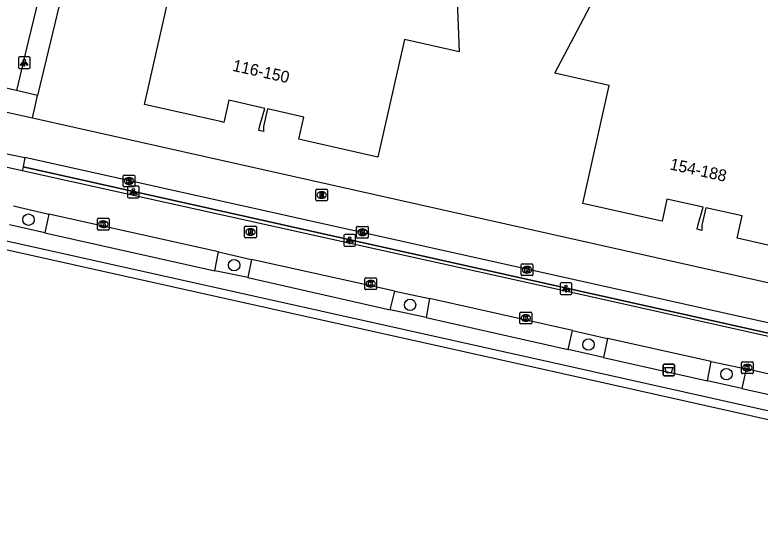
# Model space of a CAD drawing. Extents: x 162172 to 163187, y 382874 to 383684.
# Drawn here: x 162266.4 to 162330.1, y 383053.2 to 383097.4 of the extents above; entities that cross this region are included whole.
import ezdxf

# ---------------------------------------------------------------- set-up
doc = ezdxf.new("R2010")
doc.units = 0
for name, color, linetype in [('IMGEO_Afvalbak', 7, 'Continuous'), ('IMGEO_Boom', 7, 'Continuous'), ('IMGEO_Fietspad_open', 7, 'Continuous'), ('IMGEO_Kademuur', 7, 'Continuous'), ('IMGEO_Kolk', 7, 'Continuous'), ('IMGEO_Lichtpunt', 7, 'Continuous'), ('IMGEO_Muur', 7, 'Continuous'), ('IMGEO_Pand', 7, 'Continuous'), ('IMGEO_Pand_nummerreeks', 7, 'Continuous'), ('IMGEO_Rijbaan_lokaal_open', 7, 'Continuous'), ('IMGEO_Rioolput', 7, 'Continuous'), ('IMGEO_Verkeerseiland_open', 7, 'Continuous'), ('IMGEO_Voetpad_open', 7, 'Continuous')]:
    doc.layers.add(name, color=color, linetype=linetype)

msp = doc.modelspace()

# ---------------------------------------------------------------- linework, layer by layer
at = {"layer": 'IMGEO_Afvalbak'}
for p, q in [((162321.804, 383066.7), (162321.804, 383067.5)), ((162321.804, 383067.5), (162321.804, 383066.7)), ((162321.904, 383067.6), (162322.694, 383067.6)), ((162322.694, 383067.6), (162321.904, 383067.6)), ((162322.794, 383067.5), (162322.794, 383066.7)), ((162322.794, 383066.7), (162322.794, 383067.5)), ((162322.694, 383066.6), (162321.904, 383066.6)), ((162321.904, 383066.6), (162322.694, 383066.6))]:
    msp.add_line(p, q, dxfattribs=at)
msp.add_lwpolyline([(162321.947, 383067.314), (162322.651, 383067.314), (162322.502, 383066.844), (162322.096, 383066.844), (162321.947, 383067.314)], dxfattribs=at)
for centre, start, end in [((162321.904, 383067.5), 90, 180), ((162321.904, 383067.5), 90, 180), ((162322.694, 383067.5), 0, 90), ((162322.694, 383067.5), 360, 90), ((162321.904, 383066.7), 180, 270), ((162321.904, 383066.7), 180, 270), ((162322.694, 383066.7), 270, 0), ((162322.694, 383066.7), 270, 0)]:
    msp.add_arc(centre, 0.1, start, end, dxfattribs=at)
at = {"layer": 'IMGEO_Boom'}
for centre in [(162267.581, 383079.948), (162285.155, 383076.059), (162300.19, 383072.66), (162315.434, 383069.272), (162327.222, 383066.74)]:
    msp.add_circle(centre, 0.489, dxfattribs=at)
at = {"layer": 'IMGEO_Fietspad_open'}
for points in [[(162267.056, 383084.129), (162265.12, 383084.559)], [(162266.293, 383081.12), (162269.32, 383080.413)], [(162283.824, 383077.204), (162269.32, 383080.413)], [(162283.824, 383077.204), (162286.631, 383076.546)], [(162298.895, 383073.827), (162286.631, 383076.546)], [(162298.895, 383073.827), (162301.862, 383073.209)], [(162314.064, 383070.471), (162301.862, 383073.209)], [(162314.064, 383070.471), (162317.059, 383069.805)], [(162325.931, 383067.815), (162317.059, 383069.805)], [(162325.931, 383067.815), (162328.897, 383067.213)], [(162337.993, 383065.091), (162328.897, 383067.213)]]:
    msp.add_lwpolyline(points, dxfattribs=at)
at = {"layer": 'IMGEO_Kademuur'}
for points in [[(162182.996, 383097.146), (162183.031, 383097.321), (162187.251, 383096.286), (162188.296, 383095.38), (162313.416, 383067.527), (162541.309, 383016.586)], [(162569.19, 383010.669), (162568.136, 383009.792), (162380.82, 383051.66), (162313.239, 383066.765), (162187.94, 383094.645), (162186.014, 383096.385), (162186.034, 383096.464), (162182.996, 383097.146)]]:
    msp.add_lwpolyline(points, dxfattribs=at)
at = {"layer": 'IMGEO_Kolk'}
for p, q in [((162275.75, 383083.756), (162276.602, 383083.756)), ((162275.675, 383082.83), (162275.675, 383083.682)), ((162276.163, 383083.536), (162276.188, 383083.536)), ((162276.676, 383083.682), (162276.676, 383082.83)), ((162276.602, 383082.756), (162275.75, 383082.756)), ((162276.186, 383082.976), (162276.161, 383082.976)), ((162273.482, 383079.135), (162273.482, 383079.987)), ((162273.557, 383080.061), (162274.409, 383080.061)), ((162274.483, 383079.987), (162274.483, 383079.135)), ((162273.993, 383079.281), (162273.968, 383079.281)), ((162273.97, 383079.841), (162273.995, 383079.841)), ((162295.622, 383078.445), (162295.622, 383079.297)), ((162295.697, 383079.371), (162296.549, 383079.371)), ((162296.623, 383079.297), (162296.623, 383078.445)), ((162274.409, 383079.061), (162273.557, 383079.061)), ((162296.11, 383079.151), (162296.135, 383079.151)), ((162296.549, 383078.371), (162295.697, 383078.371)), ((162296.133, 383078.591), (162296.108, 383078.591)), ((162309.684, 383075.236), (162309.684, 383076.088)), ((162309.759, 383076.162), (162310.611, 383076.162)), ((162310.685, 383076.088), (162310.685, 383075.236)), ((162310.172, 383075.942), (162310.197, 383075.942)), ((162296.328, 383074.044), (162296.328, 383074.896)), ((162296.403, 383074.97), (162297.255, 383074.97)), ((162297.329, 383074.896), (162297.329, 383074.044)), ((162310.611, 383075.162), (162309.759, 383075.162)), ((162310.195, 383075.382), (162310.17, 383075.382)), ((162296.839, 383074.19), (162296.814, 383074.19)), ((162296.816, 383074.75), (162296.841, 383074.75)), ((162297.255, 383073.97), (162296.403, 383073.97)), ((162309.582, 383071.114), (162309.582, 383071.966)), ((162309.657, 383072.04), (162310.509, 383072.04)), ((162310.07, 383071.82), (162310.095, 383071.82)), ((162310.583, 383071.966), (162310.583, 383071.114)), ((162310.509, 383071.04), (162309.657, 383071.04)), ((162310.093, 383071.26), (162310.068, 383071.26)), ((162328.509, 383066.862), (162328.509, 383067.714)), ((162328.584, 383067.788), (162329.436, 383067.788)), ((162328.997, 383067.568), (162329.022, 383067.568)), ((162329.51, 383067.714), (162329.51, 383066.862)), ((162329.436, 383066.788), (162328.584, 383066.788)), ((162329.02, 383067.008), (162328.995, 383067.008))]:
    msp.add_line(p, q, dxfattribs=at)
for points in [[(162275.75, 383083.756), (162276.602, 383083.756)], [(162275.675, 383082.83), (162275.675, 383083.682)], [(162275.996, 383083.456), (162276.119, 383083.456), (162276.119, 383083.305), (162276.249, 383083.456), (162276.413, 383083.456), (162276.267, 383083.305), (162276.42, 383083.056), (162276.268, 383083.056), (162276.183, 383083.22), (162276.119, 383083.153), (162276.119, 383083.056), (162275.996, 383083.056), (162275.996, 383083.456)], [(162276.676, 383083.682), (162276.676, 383082.83)], [(162276.602, 383082.756), (162275.75, 383082.756)], [(162273.482, 383079.135), (162273.482, 383079.987)], [(162273.557, 383080.061), (162274.409, 383080.061)], [(162274.483, 383079.987), (162274.483, 383079.135)], [(162273.803, 383079.761), (162273.926, 383079.761), (162273.926, 383079.61), (162274.056, 383079.761), (162274.22, 383079.761), (162274.074, 383079.61), (162274.227, 383079.361), (162274.075, 383079.361), (162273.99, 383079.525), (162273.926, 383079.458), (162273.926, 383079.361), (162273.803, 383079.361), (162273.803, 383079.761)], [(162295.622, 383078.445), (162295.622, 383079.297)], [(162295.697, 383079.371), (162296.549, 383079.371)], [(162296.623, 383079.297), (162296.623, 383078.445)], [(162274.409, 383079.061), (162273.557, 383079.061)], [(162295.943, 383079.071), (162296.066, 383079.071), (162296.066, 383078.92), (162296.196, 383079.071), (162296.36, 383079.071), (162296.214, 383078.92), (162296.367, 383078.671), (162296.215, 383078.671), (162296.13, 383078.835), (162296.066, 383078.768), (162296.066, 383078.671), (162295.943, 383078.671), (162295.943, 383079.071)], [(162296.549, 383078.371), (162295.697, 383078.371)], [(162309.684, 383075.236), (162309.684, 383076.088)], [(162309.759, 383076.162), (162310.611, 383076.162)], [(162310.685, 383076.088), (162310.685, 383075.236)], [(162310.005, 383075.862), (162310.128, 383075.862), (162310.128, 383075.711), (162310.258, 383075.862), (162310.422, 383075.862), (162310.276, 383075.711), (162310.429, 383075.462), (162310.277, 383075.462), (162310.192, 383075.626), (162310.128, 383075.559), (162310.128, 383075.462), (162310.005, 383075.462), (162310.005, 383075.862)], [(162296.328, 383074.044), (162296.328, 383074.896)], [(162296.403, 383074.97), (162297.255, 383074.97)], [(162297.329, 383074.896), (162297.329, 383074.044)], [(162310.611, 383075.162), (162309.759, 383075.162)], [(162296.649, 383074.67), (162296.772, 383074.67), (162296.772, 383074.519), (162296.902, 383074.67), (162297.066, 383074.67), (162296.92, 383074.519), (162297.073, 383074.27), (162296.921, 383074.27), (162296.836, 383074.434), (162296.772, 383074.367), (162296.772, 383074.27), (162296.649, 383074.27), (162296.649, 383074.67)], [(162297.255, 383073.97), (162296.403, 383073.97)], [(162309.582, 383071.114), (162309.582, 383071.966)], [(162309.657, 383072.04), (162310.509, 383072.04)], [(162309.903, 383071.74), (162310.026, 383071.74), (162310.026, 383071.589), (162310.156, 383071.74), (162310.32, 383071.74), (162310.174, 383071.589), (162310.327, 383071.34), (162310.175, 383071.34), (162310.09, 383071.504), (162310.026, 383071.437), (162310.026, 383071.34), (162309.903, 383071.34), (162309.903, 383071.74)], [(162310.583, 383071.966), (162310.583, 383071.114)], [(162310.509, 383071.04), (162309.657, 383071.04)], [(162328.509, 383066.862), (162328.509, 383067.714)], [(162328.584, 383067.788), (162329.436, 383067.788)], [(162328.83, 383067.488), (162328.953, 383067.488), (162328.953, 383067.337), (162329.083, 383067.488), (162329.247, 383067.488), (162329.101, 383067.337), (162329.254, 383067.088), (162329.102, 383067.088), (162329.017, 383067.252), (162328.953, 383067.185), (162328.953, 383067.088), (162328.83, 383067.088), (162328.83, 383067.488)], [(162329.51, 383067.714), (162329.51, 383066.862)], [(162329.436, 383066.788), (162328.584, 383066.788)]]:
    msp.add_lwpolyline(points, dxfattribs=at)
for centre, start, end in [((162275.752, 383083.68), 91.55205, 178.44795), ((162275.752, 383083.68), 91.55205, 178.44795), ((162276.6, 383083.68), 1.55205, 88.44795), ((162276.6, 383083.68), 1.55205, 88.44795), ((162275.752, 383082.832), 181.55205, 268.44795), ((162275.752, 383082.832), 181.55205, 268.44795), ((162276.6, 383082.832), 271.55205, 358.44795), ((162276.6, 383082.832), 271.55205, 358.44795), ((162273.559, 383079.985), 91.55205, 178.44795), ((162273.559, 383079.985), 91.55205, 178.44795), ((162274.407, 383079.985), 1.55205, 88.44795), ((162274.407, 383079.985), 1.55205, 88.44795), ((162295.699, 383079.295), 91.55205, 178.44795), ((162295.699, 383079.295), 91.55205, 178.44795), ((162296.547, 383079.295), 1.55205, 88.44795), ((162296.547, 383079.295), 1.55205, 88.44795), ((162273.559, 383079.137), 181.55205, 268.44795), ((162273.559, 383079.137), 181.55205, 268.44795), ((162274.407, 383079.137), 271.55205, 358.44795), ((162274.407, 383079.137), 271.55205, 358.44795), ((162295.699, 383078.447), 181.55205, 268.44795), ((162295.699, 383078.447), 181.55205, 268.44795), ((162296.547, 383078.447), 271.55205, 358.44795), ((162296.547, 383078.447), 271.55205, 358.44795), ((162309.761, 383076.086), 91.55205, 178.44795), ((162309.761, 383076.086), 91.55205, 178.44795), ((162310.609, 383076.086), 1.55205, 88.44795), ((162310.609, 383076.086), 1.55205, 88.44795), ((162296.405, 383074.894), 91.55205, 178.44795), ((162296.405, 383074.894), 91.55205, 178.44795), ((162297.253, 383074.894), 1.55205, 88.44795), ((162297.253, 383074.894), 1.55205, 88.44795), ((162309.761, 383075.238), 181.55205, 268.44795), ((162309.761, 383075.238), 181.55205, 268.44795), ((162310.609, 383075.238), 271.55205, 358.44795), ((162310.609, 383075.238), 271.55205, 358.44795), ((162296.405, 383074.046), 181.55205, 268.44795), ((162296.405, 383074.046), 181.55205, 268.44795), ((162297.253, 383074.046), 271.55205, 358.44795), ((162297.253, 383074.046), 271.55205, 358.44795), ((162309.659, 383071.964), 91.55205, 178.44795), ((162309.659, 383071.964), 91.55205, 178.44795), ((162310.507, 383071.964), 1.55205, 88.44795), ((162310.507, 383071.964), 1.55205, 88.44795), ((162309.659, 383071.116), 181.55205, 268.44795), ((162309.659, 383071.116), 181.55205, 268.44795), ((162310.507, 383071.116), 271.55205, 358.44795), ((162310.507, 383071.116), 271.55205, 358.44795), ((162328.586, 383067.712), 91.55205, 178.44795), ((162328.586, 383067.712), 91.55205, 178.44795), ((162329.434, 383067.712), 1.55205, 88.44795), ((162329.434, 383067.712), 1.55205, 88.44795), ((162328.586, 383066.864), 181.55205, 268.44795), ((162328.586, 383066.864), 181.55205, 268.44795), ((162329.434, 383066.864), 271.55205, 358.44795), ((162329.434, 383066.864), 271.55205, 358.44795)]:
    msp.add_arc(centre, 0.0765, start, end, dxfattribs=at)
for centre, major_axis, ratio, start_param, end_param in [((162276.162, 383083.256), (-0.387, 0.002), 0.722429, 4.712389, 7.853982), ((162276.187, 383083.256), (-0.39, 0.002), 0.717154, 1.570796, 4.712389), ((162273.969, 383079.561), (-0.387, 0.002), 0.722429, 4.712389, 7.853982), ((162273.994, 383079.561), (-0.39, 0.002), 0.717154, 1.570796, 4.712389), ((162296.109, 383078.871), (-0.387, 0.002), 0.722429, 4.712389, 7.853982), ((162296.134, 383078.871), (-0.39, 0.002), 0.717154, 1.570796, 4.712389), ((162310.171, 383075.662), (-0.387, 0.002), 0.722429, 4.712389, 7.853982), ((162310.196, 383075.662), (-0.39, 0.002), 0.717154, 1.570796, 4.712389), ((162296.815, 383074.47), (-0.387, 0.002), 0.722429, 4.712389, 7.853982), ((162296.84, 383074.47), (-0.39, 0.002), 0.717154, 1.570796, 4.712389), ((162310.069, 383071.54), (-0.387, 0.002), 0.722429, 4.712389, 7.853982), ((162310.094, 383071.54), (-0.39, 0.002), 0.717154, 1.570796, 4.712389), ((162328.996, 383067.288), (-0.387, 0.002), 0.722429, 4.712389, 7.853982), ((162329.021, 383067.288), (-0.39, 0.002), 0.717154, 1.570796, 4.712389)]:
    msp.add_ellipse(centre, major_axis=major_axis, ratio=ratio, start_param=start_param, end_param=end_param, dxfattribs=at)
at = {"layer": 'IMGEO_Lichtpunt'}
for p, q in [((162266.723, 383093.756), (162266.723, 383092.949)), ((162266.723, 383093.756), (162266.723, 383092.949)), ((162267.625, 383093.851), (162266.817, 383093.851)), ((162267.625, 383093.851), (162266.817, 383093.851)), ((162267.719, 383092.949), (162267.719, 383093.756)), ((162267.719, 383092.949), (162267.719, 383093.756)), ((162266.817, 383092.855), (162267.625, 383092.855)), ((162266.817, 383092.855), (162267.625, 383092.855)), ((162276.054, 383082.707), (162276.054, 383081.9)), ((162276.054, 383082.707), (162276.054, 383081.9)), ((162276.956, 383082.802), (162276.148, 383082.802)), ((162276.956, 383082.802), (162276.148, 383082.802)), ((162277.05, 383081.9), (162277.05, 383082.707)), ((162277.05, 383081.9), (162277.05, 383082.707)), ((162276.148, 383081.806), (162276.956, 383081.806)), ((162276.148, 383081.806), (162276.956, 383081.806)), ((162295.425, 383078.683), (162294.617, 383078.683)), ((162295.425, 383078.683), (162294.617, 383078.683)), ((162294.523, 383078.588), (162294.523, 383077.781)), ((162294.523, 383078.588), (162294.523, 383077.781)), ((162295.519, 383077.781), (162295.519, 383078.588)), ((162295.519, 383077.781), (162295.519, 383078.588)), ((162294.617, 383077.687), (162295.425, 383077.687)), ((162294.617, 383077.687), (162295.425, 383077.687)), ((162313.02, 383074.466), (162313.02, 383073.659)), ((162313.02, 383074.466), (162313.02, 383073.659)), ((162313.922, 383074.561), (162313.114, 383074.561)), ((162313.922, 383074.561), (162313.114, 383074.561)), ((162314.016, 383073.659), (162314.016, 383074.466)), ((162314.016, 383073.659), (162314.016, 383074.466)), ((162313.114, 383073.565), (162313.922, 383073.565)), ((162313.114, 383073.565), (162313.922, 383073.565))]:
    msp.add_line(p, q, dxfattribs=at)
for points in [[(162267.097, 383093.42), (162267.136, 383093.392), (162266.948, 383093.13), (162266.91, 383093.157), (162267.097, 383093.42)], [(162267.199, 383093.372), (162267.246, 383093.372), (162267.246, 383093.05), (162267.199, 383093.05), (162267.199, 383093.372)], [(162267.309, 383093.392), (162267.347, 383093.419), (162267.534, 383093.157), (162267.495, 383093.129), (162267.309, 383093.392)], [(162276.428, 383082.371), (162276.467, 383082.343), (162276.279, 383082.081), (162276.241, 383082.108), (162276.428, 383082.371)], [(162276.53, 383082.323), (162276.577, 383082.323), (162276.577, 383082.001), (162276.53, 383082.001), (162276.53, 383082.323)], [(162276.64, 383082.343), (162276.678, 383082.37), (162276.865, 383082.108), (162276.826, 383082.08), (162276.64, 383082.343)], [(162294.897, 383078.252), (162294.936, 383078.224), (162294.748, 383077.962), (162294.71, 383077.989), (162294.897, 383078.252)], [(162294.999, 383078.204), (162295.046, 383078.204), (162295.046, 383077.882), (162294.999, 383077.882), (162294.999, 383078.204)], [(162295.109, 383078.224), (162295.147, 383078.251), (162295.334, 383077.989), (162295.295, 383077.961), (162295.109, 383078.224)], [(162313.394, 383074.13), (162313.433, 383074.102), (162313.245, 383073.84), (162313.207, 383073.867), (162313.394, 383074.13)], [(162313.496, 383074.082), (162313.543, 383074.082), (162313.543, 383073.76), (162313.496, 383073.76), (162313.496, 383074.082)], [(162313.606, 383074.102), (162313.644, 383074.129), (162313.831, 383073.867), (162313.792, 383073.839), (162313.606, 383074.102)]]:
    msp.add_lwpolyline(points, dxfattribs=at)
for centre in [(162267.222, 383093.554), (162276.553, 383082.505), (162295.022, 383078.386), (162313.519, 383074.264)]:
    msp.add_circle(centre, 0.0994, dxfattribs=at)
for centre, start, end in [((162266.817, 383093.756), 90, 180), ((162266.817, 383093.756), 90, 180), ((162267.625, 383093.756), 0, 90), ((162267.625, 383093.756), 0, 90), ((162266.817, 383092.949), 180, 270), ((162266.817, 383092.949), 180, 270), ((162267.625, 383092.949), 270, 0), ((162267.625, 383092.949), 270, 360), ((162276.148, 383082.707), 90, 180), ((162276.148, 383082.707), 90, 180), ((162276.956, 383082.707), 0, 90), ((162276.956, 383082.707), 0, 90), ((162276.148, 383081.9), 180, 270), ((162276.148, 383081.9), 180, 270), ((162276.956, 383081.9), 270, 0), ((162276.956, 383081.9), 270, 360), ((162294.617, 383078.588), 90, 180), ((162294.617, 383078.588), 90, 180), ((162295.425, 383078.588), 0, 90), ((162295.425, 383078.588), 0, 90), ((162294.617, 383077.781), 180, 270), ((162294.617, 383077.781), 180, 270), ((162295.425, 383077.781), 270, 0), ((162295.425, 383077.781), 270, 360), ((162313.114, 383074.466), 90, 180), ((162313.114, 383074.466), 90, 180), ((162313.922, 383074.466), 0, 90), ((162313.922, 383074.466), 0, 90), ((162313.114, 383073.659), 180, 270), ((162313.114, 383073.659), 180, 270), ((162313.922, 383073.659), 270, 0), ((162313.922, 383073.659), 270, 360)]:
    msp.add_arc(centre, 0.0946, start, end, dxfattribs=at)
at = {"layer": 'IMGEO_Muur'}
msp.add_lwpolyline([(162387.584, 383057.578), (162267.118, 383084.469)], dxfattribs=at)
at = {"layer": 'IMGEO_Pand'}
for points in [[(162303.917, 383106.01), (162304.381, 383094.3), (162299.71, 383095.354), (162297.444, 383085.285), (162290.928, 383086.759), (162290.681, 383086.815), (162291.107, 383088.717), (162288.013, 383089.41), (162287.678, 383087.917), (162287.68, 383087.475), (162287.26, 383087.569), (162287.354, 383087.988), (162287.785, 383089.458), (162284.691, 383090.151), (162284.266, 383088.259), (162283.986, 383088.323), (162277.508, 383089.793), (162279.771, 383099.862), (162275.11, 383100.906), (162280.553, 383111.29)], [(162341.366, 383097.566), (162341.833, 383085.858), (162337.163, 383086.917), (162334.903, 383076.836), (162328.404, 383078.31), (162328.134, 383078.371), (162328.56, 383080.273), (162325.466, 383080.966), (162325.131, 383079.473), (162325.133, 383079.031), (162324.713, 383079.125), (162324.807, 383079.544), (162325.238, 383081.014), (162322.144, 383081.707), (162321.72, 383079.816), (162321.455, 383079.876), (162314.948, 383081.342), (162317.212, 383091.411), (162312.553, 383092.454), (162318.021, 383102.852)]]:
    msp.add_lwpolyline(points, dxfattribs=at)
at = {"layer": 'IMGEO_Rijbaan_lokaal_open'}
for points in [[(162234.912, 383095.955), (162267.92, 383088.659)], [(162267.92, 383088.659), (162389.018, 383061.534)], [(162265.344, 383085.659), (162267.262, 383085.257)], [(162387.584, 383057.578), (162387.741, 383058.335), (162385.606, 383058.831), (162369.028, 383062.601), (162267.262, 383085.257)], [(162267.118, 383084.469), (162267.056, 383084.129)], [(162267.118, 383084.469), (162387.584, 383057.578)], [(162543.781, 383022.666), (162543.703, 383022.357), (162314.763, 383073.543), (162267.056, 383084.129)]]:
    msp.add_lwpolyline(points, dxfattribs=at)
at = {"layer": 'IMGEO_Rioolput'}
for p, q in [((162292.138, 383081.629), (162292.138, 383082.481)), ((162292.213, 383082.555), (162293.065, 383082.555)), ((162293.139, 383082.481), (162293.139, 383081.629)), ((162292.626, 383082.335), (162292.651, 383082.335)), ((162293.065, 383081.555), (162292.213, 383081.555)), ((162292.649, 383081.775), (162292.624, 383081.775)), ((162286.056, 383078.469), (162286.056, 383079.321)), ((162286.131, 383079.395), (162286.983, 383079.395)), ((162287.057, 383079.321), (162287.057, 383078.469)), ((162286.544, 383079.175), (162286.569, 383079.175)), ((162286.983, 383078.395), (162286.131, 383078.395)), ((162286.567, 383078.615), (162286.542, 383078.615))]:
    msp.add_line(p, q, dxfattribs=at)
for points in [[(162292.138, 383081.629), (162292.138, 383082.481)], [(162292.213, 383082.555), (162293.065, 383082.555)], [(162293.139, 383082.481), (162293.139, 383081.629)], [(162292.727, 383082.253), (162292.475, 383082.255), (162292.475, 383081.855)], [(162292.475, 383081.855), (162292.599, 383081.855), (162292.599, 383082.017), (162292.61, 383082.017)], [(162292.653, 383082.174), (162292.599, 383082.174), (162292.599, 383082.093)], [(162292.599, 383082.093), (162292.651, 383082.093)], [(162292.657, 383081.988), (162292.728, 383081.855), (162292.868, 383081.855), (162292.803, 383081.981)], [(162293.065, 383081.555), (162292.213, 383081.555)], [(162286.056, 383078.469), (162286.056, 383079.321)], [(162286.131, 383079.395), (162286.983, 383079.395)], [(162287.057, 383079.321), (162287.057, 383078.469)], [(162286.645, 383079.093), (162286.393, 383079.095), (162286.393, 383078.695)], [(162286.393, 383078.695), (162286.517, 383078.695), (162286.517, 383078.857), (162286.528, 383078.857)], [(162286.571, 383079.014), (162286.517, 383079.014), (162286.517, 383078.933)], [(162286.517, 383078.933), (162286.569, 383078.933)], [(162286.575, 383078.828), (162286.646, 383078.695), (162286.786, 383078.695), (162286.721, 383078.821)], [(162286.983, 383078.395), (162286.131, 383078.395)]]:
    msp.add_lwpolyline(points, dxfattribs=at)
for centre, radius, start, end in [((162292.215, 383082.479), 0.0765, 91.55205, 178.44795), ((162292.215, 383082.479), 0.0765, 91.55205, 178.44795), ((162293.063, 383082.479), 0.0765, 1.55205, 88.44795), ((162293.063, 383082.479), 0.0765, 1.55205, 88.44795), ((162292.609, 383081.964), 0.0533, 26.02933, 88.69889), ((162292.635, 383082.282), 0.19, 274.7715, 282.96867), ((162292.659, 383082.078), 0.0964, 77.00612, 93.18647), ((162292.673, 383082.135), 0.0378, 276.66336, 79.67722), ((162292.726, 383082.143), 0.109, 350.36119, 89.41601), ((162292.724, 383082.143), 0.112, 277.58423, 350.98172), ((162292.708, 383081.928), 0.108, 29.51342, 73.79051), ((162292.215, 383081.631), 0.0765, 181.55205, 268.44795), ((162292.215, 383081.631), 0.0765, 181.55205, 268.44795), ((162293.063, 383081.631), 0.0765, 271.55205, 358.44795), ((162293.063, 383081.631), 0.0765, 271.55205, 358.44795), ((162286.133, 383079.319), 0.0765, 91.55205, 178.44795), ((162286.133, 383079.319), 0.0765, 91.55205, 178.44795), ((162286.981, 383079.319), 0.0765, 1.55205, 88.44795), ((162286.981, 383079.319), 0.0765, 1.55205, 88.44795), ((162286.527, 383078.804), 0.0533, 26.02933, 88.69889), ((162286.553, 383079.122), 0.19, 274.7715, 282.96867), ((162286.577, 383078.918), 0.0964, 77.00612, 93.18647), ((162286.591, 383078.975), 0.0378, 276.66336, 79.67722), ((162286.644, 383078.983), 0.109, 350.36119, 89.41601), ((162286.642, 383078.983), 0.112, 277.58423, 350.98172), ((162286.626, 383078.768), 0.108, 29.51342, 73.79051), ((162286.133, 383078.471), 0.0765, 181.55205, 268.44795), ((162286.133, 383078.471), 0.0765, 181.55205, 268.44795), ((162286.981, 383078.471), 0.0765, 271.55205, 358.44795), ((162286.981, 383078.471), 0.0765, 271.55205, 358.44795)]:
    msp.add_arc(centre, radius, start, end, dxfattribs=at)
for centre, major_axis, ratio, start_param, end_param in [((162292.625, 383082.055), (-0.387, 0.002), 0.722429, 4.712389, 7.853982), ((162292.65, 383082.055), (-0.39, 0.002), 0.717154, 1.570796, 4.712389), ((162286.543, 383078.895), (-0.387, 0.002), 0.722429, 4.712389, 7.853982), ((162286.568, 383078.895), (-0.39, 0.002), 0.717154, 1.570796, 4.712389)]:
    msp.add_ellipse(centre, major_axis=major_axis, ratio=ratio, start_param=start_param, end_param=end_param, dxfattribs=at)
at = {"layer": 'IMGEO_Verkeerseiland_open'}
for points in [[(162269.32, 383080.413), (162268.969, 383078.808)], [(162283.497, 383075.583), (162283.824, 383077.204)], [(162286.631, 383076.546), (162286.334, 383074.998)], [(162298.483, 383072.254), (162298.895, 383073.827)], [(162301.862, 383073.209), (162301.557, 383071.579)], [(162313.712, 383068.843), (162314.064, 383070.471)], [(162317.059, 383069.805), (162316.725, 383068.16)], [(162325.604, 383066.179), (162325.931, 383067.815)], [(162328.897, 383067.213), (162328.55, 383065.522)]]:
    msp.add_lwpolyline(points, dxfattribs=at)
at = {"layer": 'IMGEO_Voetpad_open'}
for points in [[(162275.664, 383114.546), (162272.429, 383115.3), (162267.143, 383093.402), (162267.111, 383093.269), (162266.557, 383090.977)], [(162280.553, 383111.29), (162273.707, 383112.819), (162268.369, 383090.547)], [(162266.557, 383090.977), (162217.357, 383101.865), (162198.794, 383103.677), (162196.863, 383103.866)], [(162268.369, 383090.547), (162266.557, 383090.977)], [(162267.92, 383088.659), (162268.092, 383089.392), (162268.369, 383090.547)], [(162267.262, 383085.257), (162267.118, 383084.469)], [(162268.969, 383078.808), (162265.957, 383079.496)], [(162268.969, 383078.808), (162283.497, 383075.583)], [(162286.334, 383074.998), (162283.497, 383075.583)], [(162286.334, 383074.998), (162298.483, 383072.254)], [(162301.557, 383071.579), (162298.483, 383072.254)], [(162301.557, 383071.579), (162313.712, 383068.843)], [(162316.725, 383068.16), (162313.712, 383068.843)], [(162316.725, 383068.16), (162325.604, 383066.179)], [(162328.55, 383065.522), (162325.604, 383066.179)], [(162328.55, 383065.522), (162337.629, 383063.515)]]:
    msp.add_lwpolyline(points, dxfattribs=at)

# ---------------------------------------------------------------- texts
at = {"layer": 'IMGEO_Pand_nummerreeks'}
for s, p in [('116-150', (162284.962, 383092.673)), ('154-188', (162322.326, 383084.248))]:
    msp.add_text(s, height=1, rotation=347.40124, dxfattribs=at).set_placement(p)

doc.saveas('drawing.dxf')
